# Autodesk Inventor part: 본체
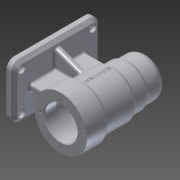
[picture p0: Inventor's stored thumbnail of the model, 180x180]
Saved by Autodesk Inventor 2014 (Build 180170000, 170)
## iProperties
Created: 2016-06
Part Number: 본체
Material: Aluminum 6061
Document SubType Name: Modeling
Designer: 601-
Density: 2.71 g/cm^3
Appearance: Aluminum - Flat
Mass: 672.364 g
Surface Area: 647.83 cm^2
Volume: 248.105 cm^3
Author: 601-
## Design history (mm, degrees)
sketch "Sketch1"
  geometry: 1 further point
sketch "Sketch2"
  geometry: L1 (-56, 35)-(56, 35); L2 (56, 35)-(56, -35); L3 (56, -35)-(-56, -35); L4 (-56, -35)-(-56, 35); L5 (56, -35)-(-56, 35); 2 further points
  constraints: 10 end point, 2 parallel, 1 coincident, 1 horizontal, 1 midpoint, 1 perpendicular
  dimensions: "d0" = 112 distance of L1.start L1.end; "d1" = 70 distance of L1.end L2.end
extrude "Extrusion1" new body sketch "Sketch2" distance "d2" = 10; taper "d3" = 0 deg
sketch "Sketch3"
  geometry: L1 (0, 70)-(0, 0) reference; C1 r 34 at (70, 35); 2 further points
  constraints: 1 centre point, 1 horizontal alignment, 1 midpoint
  dimensions: "d4" = 68 diameter of C1; "d5" = 70 distance of C1.centre point (0, 35)
extrude "Extrusion2" join sketch "Sketch3" distance "d6" = 28; taper "d7" = 0 deg
sketch "Sketch5"
  geometry: C1 r 34 at (0, 0) reference; C2 r 30 at (0, 0); 1 further point
  constraints: 1 centre point, 1 coincident
  dimensions: "d8" = 60 diameter of C2
extrude "Extrusion3" join sketch "Sketch5" distance "d9" = 39; taper "d10" = 0 deg
sketch "Sketch6"
  geometry: C1 r 30 at (0, 0) reference; C2 r 27 at (0, 0); 1 further point
  constraints: 1 centre point, 1 coincident
  dimensions: "d11" = 54 diameter of C2
extrude "Extrusion4" join sketch "Sketch6" distance "d12" = 20; taper "d13" = 0 deg
sketch "Sketch7"
  geometry: C1 r 27 at (0, 0) reference; C2 r 25 at (0, 0); 1 further point
  constraints: 1 centre point, 1 coincident
  dimensions: "d14" = 50 diameter of C2
extrude "Extrusion5" join sketch "Sketch7" distance "d15" = 25; taper "d16" = 0 deg
workplane "Work Plane2"
sketch "Sketch9"
  geometry: L1 (34, -28)-(-34, -28) reference; 3 further points
  constraints: 1 midpoint, 1 vertical alignment, 1 other
  dimensions: "d17" = 48 distance from line of L1 point (0, 20)
emboss "Emboss1" sketch "Sketch9" dims "d18" = 0.5, "d19" = 0
sketch "Sketch10"
  geometry: L1 (4, 36)-(-4, 36); L2 (-4, 36)-(-4, -36); L3 (-4, -36)-(4, -36); L4 (4, -36)-(4, 36); L5 (-4, -36)-(4, 36); L6 (25, 56)-(-25, 56) reference; 2 further points
  constraints: 10 end point, 2 parallel, 1 coincident, 1 horizontal, 1 midpoint, 1 perpendicular
  dimensions: "d21" = 20 distance between parallel lines of L6 L1; "d22" = 8 distance of L1.start L1.end
extrude "Extrusion6" join sketch "Sketch10" stored distance "d23" = 25; taper "d24" = 0 deg
sketch "Sketch11"
  geometry: L1 (-10, 4)-(-45.322, 4) reference; L2 (-10, -35)-(-10, 35) reference; L3 (-44.32, 15.509)-(-10, 28); L4 (0, 35)-(-10, 35) reference; A1 r 30 centre (-70, 0) between (-40.268, 4) and (-40.268, -4) reference; 1 further point
  constraints: 2 end point, 1 point on circle, 1 point on line
  dimensions: "d25" = 110 deg angle of L2 L3; "d26" = 7 distance from line of L4 L3.end
feature "Rib1" sketch "Sketch11" dims "d27" = 1, "d28" = 8, "d29" = 0, "d30" = 0, "d31" = 1, "d32" = 1
mirror "Mirror1"
sketch "Sketch12"
  geometry: C1 r 34 at (0, 0) reference; C2 r 21 at (0, 0); 1 further point
  constraints: 1 centre point, 1 coincident
  dimensions: "d33" = 42 diameter of C2
extrude "Extrusion7" cut sketch "Sketch12" distance "d34" = 15; taper "d35" = 0 deg
sketch "Sketch13"
  geometry: C1 r 21 at (0, 0) reference; C2 r 24 at (0, 0); 1 further point
  constraints: 1 centre point, 1 coincident
  dimensions: "d36" = 48 diameter of C2
extrude "Extrusion8" cut sketch "Sketch13" distance "d37" = 54; taper "d38" = 0 deg
sketch "Sketch14"
  geometry: C1 r 24 at (0, 0) reference; C2 r 21 at (0, 0); 1 further point
  constraints: 1 centre point, 1 coincident
  dimensions: "d39" = 42 diameter of C2
extrude "Extrusion9" cut sketch "Sketch14" distance "d40" = 12; taper "d41" = 0 deg
sketch "Sketch15"
  geometry: C1 r 21 at (0, 0) reference; C2 r 17.5 at (0, 0); 1 further point
  constraints: 1 centre point, 1 coincident
  dimensions: "d42" = 35 diameter of C2
extrude "Extrusion10" cut sketch "Sketch15" distance "d43" = 18; taper "d44" = 0 deg
sketch "Sketch16"
  geometry: C1 r 17.5 at (0, 0) reference; C2 r 16 at (0, 0); 1 further point
  constraints: 1 centre point, 1 coincident
  dimensions: "d45" = 32 diameter of C2
extrude "Extrusion11" cut sketch "Sketch16" distance "d46" = 4; taper "d47" = 0 deg
sketch "Sketch17"
  geometry: C1 r 16 at (0, 0) reference; C2 r 10.5 at (0, 0); 1 further point
  constraints: 1 centre point, 1 coincident
  dimensions: "d48" = 21 diameter of C2
extrude "Extrusion12" cut sketch "Sketch17" distance "d49" = 3; taper "d50" = 0 deg
sketch "Sketch18" dims "d51" = 52
  geometry: L1 (0, 0)-(26, 0); C1 r 21 at (0, 0) reference; C2 r 34 at (0, 0) reference; 2 further points
  constraints: 2 coincident, 2 end point, 1 horizontal, 1 horizontal alignment, 2 other
hole "Hole1" sketch "Sketch18" at (26, 0) diameter "d52" = 3.242; stored, may be unused: countersink angle "d56" = 90 deg, drill point angle "d58" = 118 deg; dims "d53" = 8, "d54" = 4, "d55" = 2, "d57" = 11
pattern_circular "Circular Pattern1" dims angle "d60" = 360 deg
fillet "Fillet1" dims "d62" = 0.3
fillet "Fillet2" dims "d63" = 3
fillet "Fillet3" dims "d64" = 10
sketch "Sketch19"
  geometry: L1 (-28, 4)-(-4, 4) reference; L2 (-4, 4)-(-4, 36) reference; L3 (-4, 36)-(4, 36) reference; L4 (4, 36)-(4, 4) reference; L5 (4, 4)-(28, 4) reference; L6 (28, 4)-(28, -4) reference; L7 (28, -4)-(4, -4) reference; L8 (4, -4)-(4, -36) reference; L9 (4, -36)-(-4, -36) reference; L10 (-4, -36)-(-4, -4) reference; L11 (-4, -4)-(-28, -4) reference; L12 (-28, -4)-(-28, 4) reference; 5 further points
hole "Hole2" sketch "Sketch19" at (-25, -46), (25, -46), (25, 46), (-25, 46) diameter "d66" = 5; stored, may be unused: countersink angle "d70" = 90 deg, drill point angle "d72" = 118 deg; dims "d67" = 8, "d68" = 9, "d69" = 4, "d71" = 11
chamfer "Chamfer1" distance "d73" = 4; stored, may be unused: second distance "d74" = 2, angle "d75" = 45 deg
fillet "Fillet5" dims "d76" = 3
fillet "Fillet6" dims "d77" = 3
fillet "Fillet7" dims "d78" = 10
fillet "Fillet8" dims "d79" = 3
fillet "Fillet9" dims "d80" = 3
fillet "Fillet17" dims "d88" = 3
fillet "Fillet18" dims "d89" = 3
fillet "Fillet19" dims "d90" = 3
fillet "Fillet20" dims "d91" = 3
chamfer "Chamfer2" distance "d92" = 1; stored, may be unused: second distance "d93" = 2, angle "d94" = 45 deg
body "Solid1"
node "Projected Loop1"
node "Projected Loop2"
node "Projected Loop3"
node "Projected Loop4"
node "Projected Loop5"
node "Projected Loop6"
node "Projected Loop7"
node "Projected Loop8"
node "Projected Loop9"
node "Projected Loop10"
node "Projected Loop11"
